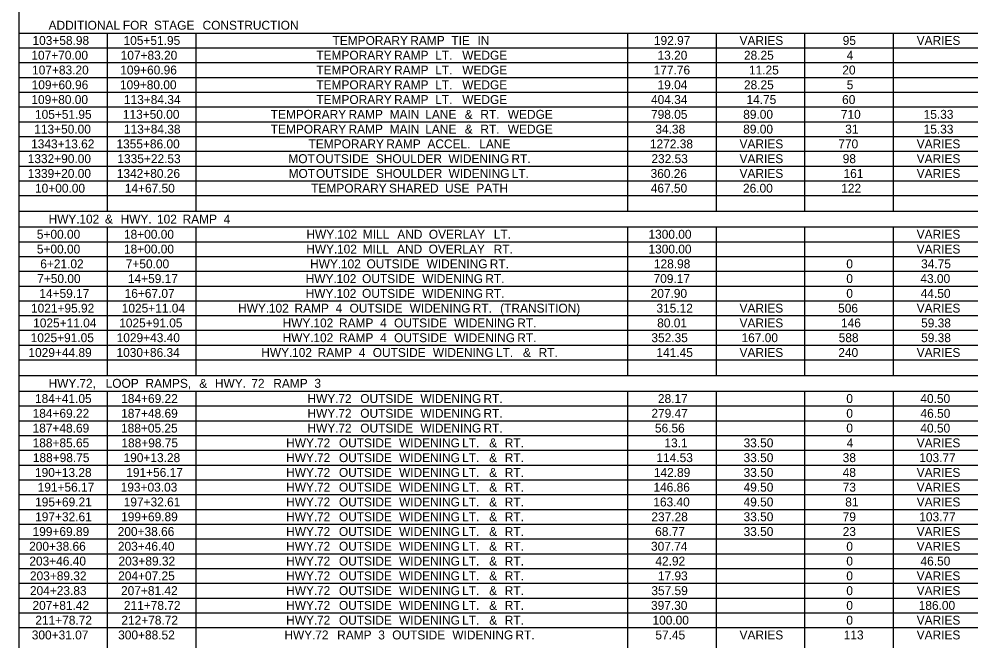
# Model space of a CAD drawing. Extents: x 1226590 to 1228573, y 151304 to 154224.
# Drawn here: x 1226590 to 1227125, y 152974 to 153322 of the extents above; entities that cross this region are included whole.
import ezdxf

# ---------------------------------------------------------------- set-up
doc = ezdxf.new("R2010")
doc.units = 0
doc.layers.add('R_Dimension', color=7, linetype='Continuous')

msp = doc.modelspace()

# ---------------------------------------------------------------- linework, layer by layer
at = {"layer": 'R_Dimension'}
for p, q in [((1226590.27, 152627.62), (1226590.27, 154214.43)), ((1226590.27, 153314.5), (1228572.93, 153314.5)), ((1226640, 153214.57), (1226640, 153314.5)), ((1226689.72, 153214.57), (1226689.72, 153314.5)), ((1226932.01, 153214.57), (1226932.01, 153314.5)), ((1226981.73, 153214.57), (1226981.73, 153314.5)), ((1227031.46, 153214.57), (1227031.46, 153314.5)), ((1227081.18, 153214.57), (1227081.18, 153314.5)), ((1226590.27, 153306.22), (1228572.93, 153306.22)), ((1226590.27, 153297.93), (1228572.93, 153297.93)), ((1226590.27, 153289.64), (1228572.93, 153289.64)), ((1226590.27, 153281.35), (1228572.93, 153281.35)), ((1226590.27, 153273.07), (1228572.93, 153273.07)), ((1226590.27, 153264.78), (1228572.93, 153264.78)), ((1226590.27, 153256.49), (1228572.93, 153256.49)), ((1226590.27, 153248.2), (1228572.93, 153248.2)), ((1226590.27, 153239.92), (1228572.93, 153239.92)), ((1226590.27, 153231.63), (1228572.93, 153231.63)), ((1226590.27, 153223.34), (1228572.93, 153223.34)), ((1226590.27, 153214.57), (1228572.93, 153214.57)), ((1226590.27, 153205.79), (1228572.93, 153205.79)), ((1226640, 153122.43), (1226640, 153205.79)), ((1226689.72, 153122.43), (1226689.72, 153205.79)), ((1226932.01, 153122.43), (1226932.01, 153205.79)), ((1226981.73, 153122.43), (1226981.73, 153205.79)), ((1227031.46, 153122.43), (1227031.46, 153205.79)), ((1227081.18, 153122.43), (1227081.18, 153205.79)), ((1226590.27, 153197.5), (1228572.93, 153197.5)), ((1226590.27, 153189.22), (1228572.93, 153189.22)), ((1226590.27, 153180.93), (1228572.93, 153180.93)), ((1226590.27, 153172.64), (1228572.93, 153172.64)), ((1226590.27, 153164.35), (1228572.93, 153164.35)), ((1226590.27, 153156.07), (1228572.93, 153156.07)), ((1226590.27, 153147.78), (1228572.93, 153147.78)), ((1226590.27, 153139.49), (1228572.93, 153139.49)), ((1226590.27, 153131.2), (1228572.93, 153131.2)), ((1226590.27, 153122.43), (1228572.93, 153122.43)), ((1226590.27, 153113.65), (1228572.93, 153113.65)), ((1226640, 152839.68), (1226640, 153113.65)), ((1226689.72, 152839.68), (1226689.72, 153113.65)), ((1226932.01, 152839.68), (1226932.01, 153113.65)), ((1226981.73, 152839.68), (1226981.73, 153113.65)), ((1227031.46, 152839.68), (1227031.46, 153113.65)), ((1227081.18, 152839.68), (1227081.18, 153113.65)), ((1226590.27, 153105.37), (1228572.93, 153105.37)), ((1226590.27, 153097.08), (1228572.93, 153097.08)), ((1226590.27, 153088.79), (1228572.93, 153088.79)), ((1226590.27, 153080.5), (1228572.93, 153080.5)), ((1226590.27, 153072.22), (1228572.93, 153072.22)), ((1226590.27, 153063.93), (1228572.93, 153063.93)), ((1226590.27, 153055.64), (1228572.93, 153055.64)), ((1226590.27, 153047.35), (1228572.93, 153047.35)), ((1226590.27, 153039.07), (1228572.93, 153039.07)), ((1226590.27, 153030.78), (1228572.93, 153030.78)), ((1226590.27, 153022.49), (1228572.93, 153022.49)), ((1226590.27, 153014.2), (1228572.93, 153014.2)), ((1226590.27, 153005.92), (1228572.93, 153005.92)), ((1226590.27, 152997.63), (1228572.93, 152997.63)), ((1226590.27, 152989.34), (1228572.93, 152989.34)), ((1226590.27, 152981.05), (1228572.93, 152981.05))]:
    msp.add_line(p, q, dxfattribs=at)

# ---------------------------------------------------------------- texts
for s, p in [('ADDITIONAL', (1226606.85, 153316.39)), (' FOR', (1226646.69, 153316.39)), (' STAGE', (1226664.17, 153316.39)), (' CONSTRUCTION', (1226691.45, 153316.39)), ('103+58.98', (1226597.81, 153307.86)), ('105+51.95', (1226648.95, 153307.86)), ('TEMPORARY', (1226766.24, 153307.86)), (' RAMP', (1226808.05, 153307.86)), (' TIE', (1226831.12, 153307.86)), (' IN', (1226845.73, 153307.86)), ('192.97', (1226946.67, 153307.86)), ('VARIES', (1226994.74, 153307.86)), ('95', (1227052.66, 153307.86)), ('VARIES', (1227094.19, 153307.86)), ('107+70.00', (1226597.2, 153299.57)), ('107+83.20', (1226647.32, 153299.57)), ('TEMPORARY', (1226757.16, 153299.57)), (' RAMP', (1226798.97, 153299.57)), (' LT.', (1226822.04, 153299.57)), (' WEDGE', (1226837.2, 153299.57)), ('13.20', (1226948.7, 153299.57)), ('28.25', (1226997.23, 153299.57)), ('4', (1227054.9, 153299.57)), ('107+83.20', (1226597.59, 153291.29)), ('109+60.96', (1226647.08, 153291.29)), ('TEMPORARY', (1226757.16, 153291.29)), (' RAMP', (1226798.97, 153291.29)), (' LT.', (1226822.04, 153291.29)), (' WEDGE', (1226837.2, 153291.29)), ('177.76', (1226946.54, 153291.29)), ('11.25', (1227000.06, 153291.29)), ('20', (1227052.44, 153291.29)), ('109+60.96', (1226597.36, 153283)), ('109+80.00', (1226646.92, 153283)), ('TEMPORARY', (1226757.16, 153283)), (' RAMP', (1226798.97, 153283)), (' LT.', (1226822.04, 153283)), (' WEDGE', (1226837.2, 153283)), ('19.04', (1226948.72, 153283)), ('28.25', (1226997.23, 153283)), ('5', (1227054.9, 153283)), ('109+80.00', (1226597.2, 153274.71)), ('113+84.34', (1226649.15, 153274.71)), ('TEMPORARY', (1226757.16, 153274.71)), (' RAMP', (1226798.97, 153274.71)), (' LT.', (1226822.04, 153274.71)), (' WEDGE', (1226837.2, 153274.71)), ('404.34', (1226945.06, 153274.71)), ('14.75', (1226998.64, 153274.71)), ('60', (1227052.32, 153274.71)), ('105+51.95', (1226599.23, 153266.42)), ('113+50.00', (1226648.54, 153266.42)), ('TEMPORARY', (1226731.57, 153266.42)), (' RAMP', (1226773.38, 153266.42)), (' MAIN', (1226796.45, 153266.42)), (' LANE', (1226816.45, 153266.42)), (' &', (1226838.62, 153266.42)), (' RT.', (1226847.4, 153266.42)), (' WEDGE', (1226862.79, 153266.42)), ('798.05', (1226945.06, 153266.42)), ('89.00', (1226996.81, 153266.42)), ('710', (1227051.62, 153266.42)), ('15.33', (1227098.09, 153266.42)), ('113+50.00', (1226598.81, 153258.14)), ('113+84.38', (1226649.15, 153258.14)), ('TEMPORARY', (1226731.57, 153258.14)), (' RAMP', (1226773.38, 153258.14)), (' MAIN', (1226796.45, 153258.14)), (' LANE', (1226816.45, 153258.14)), (' &', (1226838.62, 153258.14)), (' RT.', (1226847.4, 153258.14)), (' WEDGE', (1226862.79, 153258.14)), ('34.38', (1226947.5, 153258.14)), ('89.00', (1226996.81, 153258.14)), ('31', (1227054.08, 153258.14)), ('15.33', (1227098.09, 153258.14)), ('1343+13.62', (1226597.06, 153249.85)), ('1355+86.00', (1226644.96, 153249.85)), ('TEMPORARY', (1226752.79, 153249.85)), (' RAMP', (1226794.6, 153249.85)), (' ACCEL.', (1226817.67, 153249.85)), (' LANE', (1226846.77, 153249.85)), ('1272.38', (1226944.43, 153249.85)), ('VARIES', (1226994.74, 153249.85)), ('770', (1227050.2, 153249.85)), ('VARIES', (1227094.19, 153249.85)), ('1332+90.00', (1226595.15, 153241.56)), ('1335+22.53', (1226645.49, 153241.56)), ('MOT', (1226741.47, 153241.56)), (' OUTSIDE', (1226754.98, 153241.56)), (' SHOULDER', (1226788.72, 153241.56)), (' WIDENING', (1226829.43, 153241.56)), (' RT.', (1226864.86, 153241.56)), ('232.53', (1226945.26, 153241.56)), ('VARIES', (1226994.74, 153241.56)), ('98', (1227052.66, 153241.56)), ('VARIES', (1227094.19, 153241.56)), ('1339+20.00', (1226595.15, 153233.27)), ('1342+80.26', (1226645.15, 153233.27)), ('MOT', (1226741.59, 153233.27)), (' OUTSIDE', (1226755.1, 153233.27)), (' SHOULDER', (1226788.84, 153233.27)), (' WIDENING', (1226829.54, 153233.27)), (' LT.', (1226864.98, 153233.27)), ('360.26', (1226944.8, 153233.27)), ('VARIES', (1226994.74, 153233.27)), ('161', (1227053.13, 153233.27)), ('VARIES', (1227094.19, 153233.27)), ('10+00.00', (1226599.25, 153224.99)), ('14+67.50', (1226649.64, 153224.99)), ('TEMPORARY', (1226754.29, 153224.99)), (' SHARED', (1226796.1, 153224.99)), (' USE', (1226827.52, 153224.99)), (' PATH', (1226845.12, 153224.99)), ('467.50', (1226944.92, 153224.99)), ('26.00', (1226996.69, 153224.99)), ('122', (1227051.83, 153224.99)), ('HWY.', (1226606.85, 153207.68)), (' 102', (1226622.28, 153207.68)), (' &', (1226636.65, 153207.68)), (' HWY.', (1226645.43, 153207.68)), (' 102', (1226665.86, 153207.68)), (' RAMP', (1226680.23, 153207.68)), (' 4', (1226703.3, 153207.68)), ('5+00.00', (1226600.27, 153199.15)), ('18+00.00', (1226649.17, 153199.15)), ('HWY.', (1226751.61, 153199.15)), (' 102', (1226767.04, 153199.15)), (' MILL', (1226781.42, 153199.15)), (' AND', (1226800.75, 153199.15)), (' OVERLAY', (1226818.46, 153199.15)), (' LT.', (1226854.96, 153199.15)), ('1300.00', (1226943.62, 153199.15)), ('VARIES', (1227094.19, 153199.15)), ('5+00.00', (1226600.27, 153190.86)), ('18+00.00', (1226649.17, 153190.86)), ('HWY.', (1226751.49, 153190.86)), (' 102', (1226766.93, 153190.86)), (' MILL', (1226781.3, 153190.86)), (' AND', (1226800.63, 153190.86)), (' OVERLAY', (1226818.34, 153190.86)), (' RT.', (1226854.84, 153190.86)), ('1300.00', (1226943.62, 153190.86)), ('VARIES', (1227094.19, 153190.86)), ('6+21.02', (1226602.18, 153182.57)), ('7+50.00', (1226650.19, 153182.57)), ('HWY.', (1226753.68, 153182.57)), (' 102', (1226769.11, 153182.57)), (' OUTSIDE', (1226783.48, 153182.57)), (' WIDENING', (1226817.22, 153182.57)), (' RT.', (1226852.66, 153182.57)), ('128.98', (1226946.67, 153182.57)), ('0', (1227054.69, 153182.57)), ('34.75', (1227096.68, 153182.57)), ('7+50.00', (1226600.47, 153174.29)), ('14+59.17', (1226651.39, 153174.29)), ('HWY.', (1226751.18, 153174.29)), (' 102', (1226766.61, 153174.29)), (' OUTSIDE', (1226780.98, 153174.29)), (' WIDENING', (1226814.72, 153174.29)), (' RT.', (1226850.16, 153174.29)), ('709.17', (1226946.48, 153174.29)), ('0', (1227054.69, 153174.29)), ('43.00', (1227096.26, 153174.29)), ('14+59.17', (1226601.67, 153166)), ('16+67.07', (1226649.54, 153166)), ('HWY.', (1226751.18, 153166)), (' 102', (1226766.61, 153166)), (' OUTSIDE', (1226780.98, 153166)), (' WIDENING', (1226814.72, 153166)), (' RT.', (1226850.16, 153166)), ('207.90', (1226944.84, 153166)), ('0', (1227054.69, 153166)), ('44.50', (1227096.46, 153166)), ('1021+95.92', (1226596.98, 153157.71)), ('1025+11.04', (1226647.93, 153157.71)), ('HWY.', (1226713.25, 153157.71)), (' 102', (1226728.68, 153157.71)), (' RAMP', (1226743.05, 153157.71)), (' 4', (1226766.12, 153157.71)), (' OUTSIDE', (1226773.95, 153157.71)), (' WIDENING', (1226807.69, 153157.71)), (' RT.', (1226843.13, 153157.71)), (' (TRANSITION)', (1226858.52, 153157.71)), ('315.12', (1226948.09, 153157.71)), ('VARIES', (1226994.74, 153157.71)), ('506', (1227050.08, 153157.71)), ('VARIES', (1227094.19, 153157.71)), ('1025+11.04', (1226598.2, 153149.42)), ('1025+91.05', (1226646.51, 153149.42)), ('HWY.', (1226738.23, 153149.42)), (' 102', (1226753.66, 153149.42)), (' RAMP', (1226768.03, 153149.42)), (' 4', (1226791.1, 153149.42)), (' OUTSIDE', (1226798.93, 153149.42)), (' WIDENING', (1226832.67, 153149.42)), (' RT.', (1226868.11, 153149.42)), ('80.01', (1226948.52, 153149.42)), ('VARIES', (1226994.74, 153149.42)), ('146', (1227051.69, 153149.42)), ('59.38', (1227096.68, 153149.42)), ('1025+91.05', (1226596.79, 153141.14)), ('1029+43.40', (1226645.07, 153141.14)), ('HWY.', (1226738.23, 153141.14)), (' 102', (1226753.66, 153141.14)), (' RAMP', (1226768.03, 153141.14)), (' 4', (1226791.1, 153141.14)), (' OUTSIDE', (1226798.93, 153141.14)), (' WIDENING', (1226832.67, 153141.14)), (' RT.', (1226868.11, 153141.14)), ('352.35', (1226945.26, 153141.14)), ('167.00', (1226995.87, 153141.14)), ('588', (1227050.41, 153141.14)), ('59.38', (1227096.68, 153141.14)), ('1029+44.89', (1226595.55, 153132.85)), ('1030+86.34', (1226644.98, 153132.85)), ('HWY.', (1226726.26, 153132.85)), (' 102', (1226741.69, 153132.85)), (' RAMP', (1226756.06, 153132.85)), (' 4', (1226779.13, 153132.85)), (' OUTSIDE', (1226786.97, 153132.85)), (' WIDENING', (1226820.71, 153132.85)), (' LT.', (1226856.14, 153132.85)), (' &', (1226871.3, 153132.85)), (' RT.', (1226880.08, 153132.85)), ('141.45', (1226948.09, 153132.85)), ('VARIES', (1226994.74, 153132.85)), ('240', (1227050.2, 153132.85)), ('VARIES', (1227094.19, 153132.85)), ('HWY.', (1226606.85, 153115.54)), (' 72,', (1226622.28, 153115.54)), (' LOOP', (1226637.04, 153115.54)), (' RAMPS,', (1226659.4, 153115.54)), (' &', (1226689.6, 153115.54)), (' HWY.', (1226698.38, 153115.54)), (' 72', (1226718.81, 153115.54)), (' RAMP', (1226731.14, 153115.54)), (' 3', (1226754.21, 153115.54)), ('184+41.05', (1226599.23, 153107.01)), ('184+69.22', (1226647.61, 153107.01)), ('HWY.', (1226752.2, 153107.01)), (' 72', (1226767.64, 153107.01)), (' OUTSIDE', (1226779.96, 153107.01)), (' WIDENING', (1226813.7, 153107.01)), (' RT.', (1226849.13, 153107.01)), ('28.17', (1226948.92, 153107.01)), ('0', (1227054.69, 153107.01)), ('40.50', (1227096.26, 153107.01)), ('184+69.22', (1226597.89, 153098.72)), ('187+48.69', (1226647.59, 153098.72)), ('HWY.', (1226752.2, 153098.72)), (' 72', (1226767.64, 153098.72)), (' OUTSIDE', (1226779.96, 153098.72)), (' WIDENING', (1226813.7, 153098.72)), (' RT.', (1226849.13, 153098.72)), ('279.47', (1226945.26, 153098.72)), ('0', (1227054.69, 153098.72)), ('46.50', (1227096.34, 153098.72)), ('187+48.69', (1226597.87, 153090.44)), ('188+05.25', (1226647.53, 153090.44)), ('HWY.', (1226752.2, 153090.44)), (' 72', (1226767.64, 153090.44)), (' OUTSIDE', (1226779.96, 153090.44)), (' WIDENING', (1226813.7, 153090.44)), (' RT.', (1226849.13, 153090.44)), ('56.56', (1226947.24, 153090.44)), ('0', (1227054.69, 153090.44)), ('40.50', (1227096.26, 153090.44)), ('188+85.65', (1226597.89, 153082.15)), ('188+98.75', (1226647.73, 153082.15)), ('HWY.', (1226740.23, 153082.15)), (' 72', (1226755.67, 153082.15)), (' OUTSIDE', (1226767.99, 153082.15)), (' WIDENING', (1226801.73, 153082.15)), (' LT.', (1226837.16, 153082.15)), (' &', (1226852.32, 153082.15)), (' RT.', (1226861.1, 153082.15)), ('13.1', (1226952.58, 153082.15)), ('33.50', (1226997.01, 153082.15)), ('4', (1227054.9, 153082.15)), ('VARIES', (1227094.19, 153082.15)), ('188+98.75', (1226598.01, 153073.86)), ('190+13.28', (1226648.95, 153073.86)), ('HWY.', (1226740.23, 153073.86)), (' 72', (1226755.67, 153073.86)), (' OUTSIDE', (1226767.99, 153073.86)), (' WIDENING', (1226801.73, 153073.86)), (' LT.', (1226837.16, 153073.86)), (' &', (1226852.32, 153073.86)), (' RT.', (1226861.1, 153073.86)), ('114.53', (1226948.09, 153073.86)), ('33.50', (1226997.01, 153073.86)), ('38', (1227052.66, 153073.86)), ('103.77', (1227095.65, 153073.86)), ('190+13.28', (1226599.23, 153065.57)), ('191+56.17', (1226650.45, 153065.57)), ('HWY.', (1226740.23, 153065.57)), (' 72', (1226755.67, 153065.57)), (' OUTSIDE', (1226767.99, 153065.57)), (' WIDENING', (1226801.73, 153065.57)), (' LT.', (1226837.16, 153065.57)), (' &', (1226852.32, 153065.57)), (' RT.', (1226861.1, 153065.57)), ('142.89', (1226946.65, 153065.57)), ('33.50', (1226997.01, 153065.57)), ('48', (1227052.66, 153065.57)), ('VARIES', (1227094.19, 153065.57)), ('191+56.17', (1226600.72, 153057.29)), ('193+03.03', (1226647.34, 153057.29)), ('HWY.', (1226740.23, 153057.29)), (' 72', (1226755.67, 153057.29)), (' OUTSIDE', (1226767.99, 153057.29)), (' WIDENING', (1226801.73, 153057.29)), (' LT.', (1226837.16, 153057.29)), (' &', (1226852.32, 153057.29)), (' RT.', (1226861.1, 153057.29)), ('146.86', (1226946.42, 153057.29)), ('49.50', (1226997.01, 153057.29)), ('73', (1227052.66, 153057.29)), ('VARIES', (1227094.19, 153057.29)), ('195+69.21', (1226599.31, 153049)), ('197+32.61', (1226649.03, 153049)), ('HWY.', (1226740.23, 153049)), (' 72', (1226755.67, 153049)), (' OUTSIDE', (1226767.99, 153049)), (' WIDENING', (1226801.73, 153049)), (' LT.', (1226837.16, 153049)), (' &', (1226852.32, 153049)), (' RT.', (1226861.1, 153049)), ('163.40', (1226946.34, 153049)), ('49.50', (1226997.01, 153049)), ('81', (1227054.08, 153049)), ('VARIES', (1227094.19, 153049)), ('197+32.61', (1226599.31, 153040.71)), ('199+69.89', (1226647.59, 153040.71)), ('HWY.', (1226740.23, 153040.71)), (' 72', (1226755.67, 153040.71)), (' OUTSIDE', (1226767.99, 153040.71)), (' WIDENING', (1226801.73, 153040.71)), (' LT.', (1226837.16, 153040.71)), (' &', (1226852.32, 153040.71)), (' RT.', (1226861.1, 153040.71)), ('237.28', (1226945.26, 153040.71)), ('33.50', (1226997.01, 153040.71)), ('79', (1227052.64, 153040.71)), ('103.77', (1227095.65, 153040.71)), ('199+69.89', (1226597.87, 153032.42)), ('200+38.66', (1226645.66, 153032.42)), ('HWY.', (1226740.23, 153032.42)), (' 72', (1226755.67, 153032.42)), (' OUTSIDE', (1226767.99, 153032.42)), (' WIDENING', (1226801.73, 153032.42)), (' LT.', (1226837.16, 153032.42)), (' &', (1226852.32, 153032.42)), (' RT.', (1226861.1, 153032.42)), ('68.77', (1226947.38, 153032.42)), ('33.50', (1226997.01, 153032.42)), ('23', (1227052.66, 153032.42)), ('VARIES', (1227094.19, 153032.42)), ('200+38.66', (1226595.94, 153024.14)), ('203+46.40', (1226645.78, 153024.14)), ('HWY.', (1226740.23, 153024.14)), (' 72', (1226755.67, 153024.14)), (' OUTSIDE', (1226767.99, 153024.14)), (' WIDENING', (1226801.73, 153024.14)), (' LT.', (1226837.16, 153024.14)), (' &', (1226852.32, 153024.14)), (' RT.', (1226861.1, 153024.14)), ('307.74', (1226945.06, 153024.14)), ('0', (1227054.69, 153024.14)), ('VARIES', (1227094.19, 153024.14)), ('203+46.40', (1226596.06, 153015.85)), ('203+89.32', (1226646.12, 153015.85)), ('HWY.', (1226740.23, 153015.85)), (' 72', (1226755.67, 153015.85)), (' OUTSIDE', (1226767.99, 153015.85)), (' WIDENING', (1226801.73, 153015.85)), (' LT.', (1226837.16, 153015.85)), (' &', (1226852.32, 153015.85)), (' RT.', (1226861.1, 153015.85)), ('42.92', (1226947.5, 153015.85)), ('0', (1227054.69, 153015.85)), ('46.50', (1227096.34, 153015.85)), ('203+89.32', (1226596.39, 153007.56)), ('204+07.25', (1226645.92, 153007.56)), ('HWY.', (1226740.23, 153007.56)), (' 72', (1226755.67, 153007.56)), (' OUTSIDE', (1226767.99, 153007.56)), (' WIDENING', (1226801.73, 153007.56)), (' LT.', (1226837.16, 153007.56)), (' &', (1226852.32, 153007.56)), (' RT.', (1226861.1, 153007.56)), ('17.93', (1226948.92, 153007.56)), ('0', (1227054.69, 153007.56)), ('VARIES', (1227094.19, 153007.56)), ('204+23.83', (1226596.39, 152999.27)), ('207+81.42', (1226647.53, 152999.27)), ('HWY.', (1226740.23, 152999.27)), (' 72', (1226755.67, 152999.27)), (' OUTSIDE', (1226767.99, 152999.27)), (' WIDENING', (1226801.73, 152999.27)), (' LT.', (1226837.16, 152999.27)), (' &', (1226852.32, 152999.27)), (' RT.', (1226861.1, 152999.27)), ('357.59', (1226945.24, 152999.27)), ('0', (1227054.69, 152999.27)), ('VARIES', (1227094.19, 152999.27)), ('207+81.42', (1226597.81, 152990.99)), ('211+78.72', (1226649.15, 152990.99)), ('HWY.', (1226740.23, 152990.99)), (' 72', (1226755.67, 152990.99)), (' OUTSIDE', (1226767.99, 152990.99)), (' WIDENING', (1226801.73, 152990.99)), (' LT.', (1226837.16, 152990.99)), (' &', (1226852.32, 152990.99)), (' RT.', (1226861.1, 152990.99)), ('397.30', (1226945.04, 152990.99)), ('0', (1227054.69, 152990.99)), ('186.00', (1227095.32, 152990.99)), ('211+78.72', (1226599.42, 152982.7)), ('212+78.72', (1226647.73, 152982.7)), ('HWY.', (1226740.23, 152982.7)), (' 72', (1226755.67, 152982.7)), (' OUTSIDE', (1226767.99, 152982.7)), (' WIDENING', (1226801.73, 152982.7)), (' LT.', (1226837.16, 152982.7)), (' &', (1226852.32, 152982.7)), (' RT.', (1226861.1, 152982.7)), ('100.00', (1226945.87, 152982.7)), ('0', (1227054.69, 152982.7)), ('VARIES', (1227094.19, 152982.7)), ('300+31.07', (1226597.42, 152974.41)), ('300+88.52', (1226645.92, 152974.41)), ('HWY.', (1226739.25, 152974.41)), (' 72', (1226754.68, 152974.41)), (' RAMP', (1226767.01, 152974.41)), (' 3', (1226790.08, 152974.41)), (' OUTSIDE', (1226797.91, 152974.41)), (' WIDENING', (1226831.65, 152974.41)), (' RT.', (1226867.08, 152974.41)), ('57.45', (1226947.5, 152974.41)), ('VARIES', (1226994.74, 152974.41)), ('113', (1227053.25, 152974.41)), ('VARIES', (1227094.19, 152974.41))]:
    msp.add_text(s, height=5, dxfattribs=at).set_placement(p)

doc.saveas('drawing.dxf')
